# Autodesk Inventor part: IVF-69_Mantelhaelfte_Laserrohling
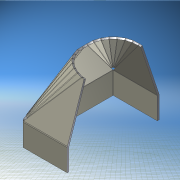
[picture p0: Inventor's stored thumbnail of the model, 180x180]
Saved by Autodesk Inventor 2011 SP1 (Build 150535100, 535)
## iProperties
Created: 2012-03
Part Number: IVF-69_Mantelhaelfte_Laserrohling
Material: Standard
Document SubType Name: Blech
Designer: Gawin
Density: 1 g/cm^3
Sheet Metal Rule: Standard_mm
Mass: 232.399 g
Surface Area: 1210.43 cm^2
Volume: 232.399 cm^3
Flat Pattern Width: 20.7013 cm
Flat Pattern Length: 41.9254 cm
Flat Pattern Area: 867.91 cm^2
Sheet Metal Width: 207,013 mm
Sheet Metal Length: 419,254 mm
Sheet Metal Area: 86791,005 mm^2
Author: Gawin
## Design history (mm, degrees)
derived "IVF-69_Mantelhaelfte_gefraest.ipt"
feature "Verdickung1" dims "d1" = 4 (= Stärke), "d2" = 4 (= Stärke)
tag "Bezeichnung1"
feature "Volumenkörper1::IVF-69_Mantelhaelfte_gefraest.ipt"
node "Flächen1"
node "Volumenkörper2"
feature "Definition1"
other parameters: "Stärke" = 4, "KFaktor" = 4.4, "Biegeradius" = 4 (= Stärke), "BreiteBiegungsfreistellung" = 4 (= Stärke), "TiefeBiegungsfreistellung" = 2 (= 0.5 x Stärke), "GrößeEckenfreistellung" = 16 (= 4 x Stärke), "AbstandVerbindung" = 0.01, "MinimalRest" = 8 (= 2 x Stärke), "Übergangsradius" = 4 (= Biegeradius), "JacobiRadiusGröße" = 4 (= Biegeradius), "Abstandsgröße" = 4 (= Stärke), "Abstandsgröße" = 4, "Biegeradius" = 4, "BreiteBiegungsfreistellung" = 4, "GrößeEckenfreistellung" = 16, "JacobiRadiusGröße" = 4, "MinimalRest" = 8, "Stärke" = 4, "TiefeBiegungsfreistellung" = 2, "Übergangsradius" = 4
